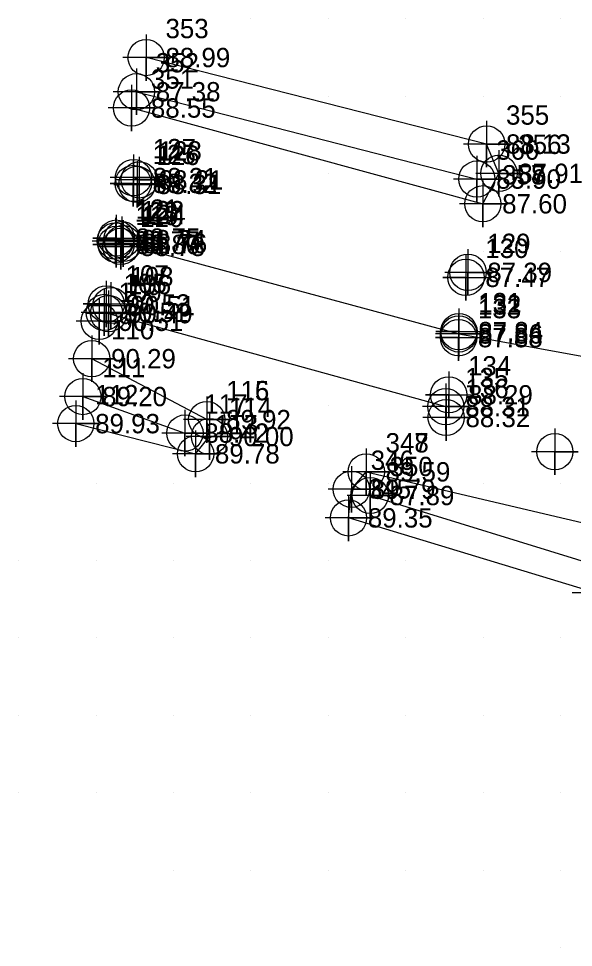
# Model space of a CAD drawing. Extents: x 1988140 to 1988766, y 249950 to 250250.
# Drawn here: x 1988140 to 1988211.7, y 249980 to 250100.1 of the extents above; entities that cross this region are included whole.
import ezdxf

# ---------------------------------------------------------------- set-up
doc = ezdxf.new("R2010")
doc.units = 0
for name, color, linetype in [('Exist DTM Breakline', 7, 'Continuous'), ('Exist DTM Breakline Cogo Elevation', 7, 'Continuous'), ('Exist DTM Breakline Cogo Number', 7, 'Continuous'), ('Exist DTM Breakline Cogo Point CELL', 7, 'Continuous'), ('Exist DTM Crownline', 7, 'Continuous'), ('Exist DTM Crownline Cogo Elevation', 7, 'Continuous'), ('Exist DTM Crownline Cogo Number', 7, 'Continuous'), ('Exist DTM Crownline Cogo Point CELL', 7, 'Continuous'), ('Exist DTM QL2 LIDAR Elevation Point', 7, 'Continuous'), ('Exist DTM Regular Point CELL', 7, 'Continuous'), ('Exist DTM Regular Point Cogo Elevation', 7, 'Continuous'), ('Exist DTM Regular Point Cogo Number', 7, 'Continuous'), ('Exist Roads EOP', 7, 'Continuous'), ('Exist Roads EOP Cogo Elevation', 7, 'Continuous'), ('Exist Roads EOP Cogo Number', 7, 'Continuous'), ('Exist Roads EOP Cogo Point CELL', 7, 'Continuous'), ('Exist Roads EOT', 7, 'Continuous'), ('Exist Roads EOT Cogo Elevation', 7, 'Continuous'), ('Exist Roads EOT Cogo Number', 7, 'Continuous'), ('Exist Roads EOT Cogo Point CELL', 7, 'Continuous')]:
    doc.layers.add(name, color=color, linetype=linetype)

msp = doc.modelspace()

# ---------------------------------------------------------------- linework, layer by layer
at = {"layer": 'Exist DTM Breakline'}
for p, q in [((1988155.2175, 250090.595), (1988199.1883, 250079.3107)), ((1988148.3042, 250051.201), (1988161.4866, 250046.4785))]:
    msp.add_line(p, q, dxfattribs=at)
for points in [[(1988154.5908, 250088.495), (1988199.964, 250076.113), (1988202.0406, 250080.0498), (1988200.4597, 250083.8363), (1988156.4732, 250095.0151)], [(1988147.3906, 250047.7015), (1988162.863, 250043.7963), (1988164.6596, 250046.0369), (1988164.3027, 250048.2184), (1988149.4523, 250056.0932)], [(1988182.6136, 250035.5158), (1988182.9813, 250039.2171), (1988184.903, 250041.4732), (1988219.3187, 250033.3718), (1988254.9783, 250021.8401), (1988300.1272, 250011.0374)], [(1988185.4236, 250038.4105), (1988216.1279, 250028.952), (1988254.719, 250017.0301), (1988298.2155, 250005.7241)], [(1988297.226, 250002.9987), (1988255.3705, 250011.301), (1988214.5049, 250025.8516), (1988182.6136, 250035.5158)]]:
    msp.add_lwpolyline(points, dxfattribs=at)
at = {"layer": 'Exist DTM Breakline Cogo Point CELL'}
for points in [[(1988156.4732, 250098.0151), (1988156.4732, 250092.0151), (1988156.4732, 250095.0151), (1988159.4732, 250095.0151), (1988153.4732, 250095.0151)], [(1988155.2175, 250093.595), (1988155.2175, 250087.595), (1988155.2175, 250090.595), (1988158.2175, 250090.595), (1988152.2175, 250090.595)], [(1988154.5908, 250091.495), (1988154.5908, 250085.495), (1988154.5908, 250088.495), (1988157.5908, 250088.495), (1988151.5908, 250088.495)], [(1988200.4597, 250086.8363), (1988200.4597, 250080.8363), (1988200.4597, 250083.8363), (1988203.4597, 250083.8363), (1988197.4597, 250083.8363)], [(1988199.1883, 250082.3107), (1988199.1883, 250076.3107), (1988199.1883, 250079.3107), (1988202.1883, 250079.3107), (1988196.1883, 250079.3107)], [(1988202.0406, 250083.0498), (1988202.0406, 250077.0498), (1988202.0406, 250080.0498), (1988205.0406, 250080.0498), (1988199.0406, 250080.0498)], [(1988199.964, 250079.113), (1988199.964, 250073.113), (1988199.964, 250076.113), (1988202.964, 250076.113), (1988196.964, 250076.113)], [(1988199.964, 250079.113), (1988199.964, 250073.113), (1988199.964, 250076.113), (1988202.964, 250076.113), (1988196.964, 250076.113)], [(1988149.4523, 250059.0932), (1988149.4523, 250053.0932), (1988149.4523, 250056.0932), (1988152.4523, 250056.0932), (1988146.4523, 250056.0932)], [(1988148.3042, 250054.201), (1988148.3042, 250048.201), (1988148.3042, 250051.201), (1988151.3042, 250051.201), (1988145.3042, 250051.201)], [(1988164.3027, 250051.2184), (1988164.3027, 250045.2184), (1988164.3027, 250048.2184), (1988167.3027, 250048.2184), (1988161.3027, 250048.2184)], [(1988164.3027, 250051.2184), (1988164.3027, 250045.2184), (1988164.3027, 250048.2184), (1988167.3027, 250048.2184), (1988161.3027, 250048.2184)], [(1988147.3906, 250050.7015), (1988147.3906, 250044.7015), (1988147.3906, 250047.7015), (1988150.3906, 250047.7015), (1988144.3906, 250047.7015)], [(1988161.4866, 250049.4785), (1988161.4866, 250043.4785), (1988161.4866, 250046.4785), (1988164.4866, 250046.4785), (1988158.4866, 250046.4785)], [(1988164.6596, 250049.0369), (1988164.6596, 250043.0369), (1988164.6596, 250046.0369), (1988167.6596, 250046.0369), (1988161.6596, 250046.0369)], [(1988162.863, 250046.7963), (1988162.863, 250040.7963), (1988162.863, 250043.7963), (1988165.863, 250043.7963), (1988159.863, 250043.7963)], [(1988184.903, 250044.4732), (1988184.903, 250038.4732), (1988184.903, 250041.4732), (1988187.903, 250041.4732), (1988181.903, 250041.4732)], [(1988184.903, 250044.4732), (1988184.903, 250038.4732), (1988184.903, 250041.4732), (1988187.903, 250041.4732), (1988181.903, 250041.4732)], [(1988182.9813, 250042.2171), (1988182.9813, 250036.2171), (1988182.9813, 250039.2171), (1988185.9813, 250039.2171), (1988179.9813, 250039.2171)], [(1988185.4236, 250041.4105), (1988185.4236, 250035.4105), (1988185.4236, 250038.4105), (1988188.4236, 250038.4105), (1988182.4236, 250038.4105)], [(1988182.6136, 250038.5158), (1988182.6136, 250032.5158), (1988182.6136, 250035.5158), (1988185.6136, 250035.5158), (1988179.6136, 250035.5158)], [(1988214.5049, 250028.8516), (1988214.5049, 250022.8516), (1988214.5049, 250025.8516), (1988217.5049, 250025.8516), (1988211.5049, 250025.8516)]]:
    msp.add_lwpolyline(points, dxfattribs=at)
for centre in [(1988156.4732, 250095.0151), (1988155.2175, 250090.595), (1988154.5908, 250088.495), (1988200.4597, 250083.8363), (1988202.0406, 250080.0498), (1988199.1883, 250079.3107), (1988199.964, 250076.113), (1988199.964, 250076.113), (1988149.4523, 250056.0932), (1988148.3042, 250051.201), (1988147.3906, 250047.7015), (1988164.3027, 250048.2184), (1988164.3027, 250048.2184), (1988161.4866, 250046.4785), (1988164.6596, 250046.0369), (1988162.863, 250043.7963), (1988184.903, 250041.4732), (1988184.903, 250041.4732), (1988182.9813, 250039.2171), (1988185.4236, 250038.4105), (1988182.6136, 250035.5158)]:
    msp.add_circle(centre, 2.344, dxfattribs=at)
at = {"layer": 'Exist DTM Crownline'}
msp.add_line((1988196.8572, 250059.2912), (1988232.2445, 250052.8974), dxfattribs=at)
msp.add_lwpolyline([(1988152.5012, 250071.3032), (1988196.8572, 250059.2912)], dxfattribs=at)
at = {"layer": 'Exist DTM Crownline Cogo Point CELL'}
for points in [[(1988152.5012, 250074.3032), (1988152.5012, 250068.3032), (1988152.5012, 250071.3032), (1988155.5012, 250071.3032), (1988149.5012, 250071.3032)], [(1988153.4965, 250073.9775), (1988153.4965, 250067.9775), (1988153.4965, 250070.9775), (1988156.4965, 250070.9775), (1988150.4965, 250070.9775)], [(1988196.8572, 250062.2912), (1988196.8572, 250056.2912), (1988196.8572, 250059.2912), (1988199.8572, 250059.2912), (1988193.8572, 250059.2912)]]:
    msp.add_lwpolyline(points, dxfattribs=at)
for centre in [(1988152.5012, 250071.3032), (1988153.4965, 250070.9775), (1988196.8572, 250059.2912)]:
    msp.add_circle(centre, 2.344, dxfattribs=at)
at = {"layer": 'Exist DTM QL2 LIDAR Elevation Point'}
for p, q in [((1988160, 250100), (1988160, 250100)), ((1988170, 250100), (1988170, 250100)), ((1988180, 250100), (1988180, 250100)), ((1988190, 250100), (1988190, 250100)), ((1988200, 250100), (1988200, 250100)), ((1988210, 250100), (1988210, 250100)), ((1988180, 250090), (1988180, 250090)), ((1988190, 250090), (1988190, 250090)), ((1988200, 250090), (1988200, 250090)), ((1988210, 250090), (1988210, 250090)), ((1988160, 250080), (1988160, 250080)), ((1988180, 250080), (1988180, 250080)), ((1988210, 250080), (1988210, 250080)), ((1988200, 250070), (1988200, 250070)), ((1988210, 250070), (1988210, 250070)), ((1988150, 250060), (1988150, 250060)), ((1988170, 250050), (1988170, 250050)), ((1988180, 250050), (1988180, 250050)), ((1988150, 250040), (1988150, 250040)), ((1988160, 250040), (1988160, 250040)), ((1988170, 250040), (1988170, 250040)), ((1988180, 250040), (1988180, 250040)), ((1988200, 250040), (1988200, 250040)), ((1988210, 250040), (1988210, 250040)), ((1988140, 250030), (1988140, 250030)), ((1988150, 250030), (1988150, 250030)), ((1988160, 250030), (1988160, 250030)), ((1988170, 250030), (1988170, 250030)), ((1988180, 250030), (1988180, 250030)), ((1988190, 250030), (1988190, 250030)), ((1988140, 250020), (1988140, 250020)), ((1988150, 250020), (1988150, 250020)), ((1988160, 250020), (1988160, 250020)), ((1988170, 250020), (1988170, 250020)), ((1988180, 250020), (1988180, 250020)), ((1988190, 250020), (1988190, 250020)), ((1988200, 250020), (1988200, 250020)), ((1988210, 250020), (1988210, 250020)), ((1988140, 250010), (1988140, 250010)), ((1988150, 250010), (1988150, 250010)), ((1988160, 250010), (1988160, 250010)), ((1988170, 250010), (1988170, 250010)), ((1988180, 250010), (1988180, 250010)), ((1988190, 250010), (1988190, 250010)), ((1988200, 250010), (1988200, 250010)), ((1988210, 250010), (1988210, 250010)), ((1988140, 250000), (1988140, 250000)), ((1988150, 250000), (1988150, 250000)), ((1988160, 250000), (1988160, 250000)), ((1988170, 250000), (1988170, 250000)), ((1988180, 250000), (1988180, 250000)), ((1988190, 250000), (1988190, 250000)), ((1988200, 250000), (1988200, 250000)), ((1988210, 250000), (1988210, 250000)), ((1988160, 249990), (1988160, 249990)), ((1988170, 249990), (1988170, 249990)), ((1988180, 249990), (1988180, 249990)), ((1988190, 249990), (1988190, 249990)), ((1988200, 249990), (1988200, 249990)), ((1988210, 249990), (1988210, 249990)), ((1988210, 249980), (1988210, 249980))]:
    msp.add_line(p, q, dxfattribs=at)
at = {"layer": 'Exist DTM Regular Point CELL'}
for points in [[(1988150.4184, 250063.925), (1988150.4184, 250057.925), (1988150.4184, 250060.925), (1988153.4184, 250060.925), (1988147.4184, 250060.925)], [(1988195.2245, 250051.4959), (1988195.2245, 250045.4959), (1988195.2245, 250048.4959), (1988198.2245, 250048.4959), (1988192.2245, 250048.4959)], [(1988209.2644, 250047.0711), (1988209.2644, 250041.0711), (1988209.2644, 250044.0711), (1988212.2644, 250044.0711), (1988206.2644, 250044.0711)]]:
    msp.add_lwpolyline(points, dxfattribs=at)
for centre in [(1988150.4184, 250060.925), (1988195.2245, 250048.4959), (1988209.2644, 250044.0711)]:
    msp.add_circle(centre, 2.344, dxfattribs=at)
at = {"layer": 'Exist Roads EOP'}
for p, q in [((1988154.8364, 250079.4949), (1988155.5906, 250079.2044)), ((1988151.0639, 250062.0678), (1988151.6279, 250061.9198)), ((1988151.6279, 250061.9198), (1988195.1839, 250049.8966))]:
    msp.add_line(p, q, dxfattribs=at)
at = {"layer": 'Exist Roads EOP Cogo Point CELL'}
for points in [[(1988154.8364, 250082.4949), (1988154.8364, 250076.4949), (1988154.8364, 250079.4949), (1988157.8364, 250079.4949), (1988151.8364, 250079.4949)], [(1988155.5906, 250082.2044), (1988155.5906, 250076.2044), (1988155.5906, 250079.2044), (1988158.5906, 250079.2044), (1988152.5906, 250079.2044)], [(1988198.0437, 250070.25), (1988198.0437, 250064.25), (1988198.0437, 250067.25), (1988201.0437, 250067.25), (1988195.0437, 250067.25)], [(1988151.0639, 250065.0678), (1988151.0639, 250059.0678), (1988151.0639, 250062.0678), (1988154.0639, 250062.0678), (1988148.0639, 250062.0678)], [(1988151.6279, 250064.9198), (1988151.6279, 250058.9198), (1988151.6279, 250061.9198), (1988154.6279, 250061.9198), (1988148.6279, 250061.9198)], [(1988195.1839, 250052.8966), (1988195.1839, 250046.8966), (1988195.1839, 250049.8966), (1988198.1839, 250049.8966), (1988192.1839, 250049.8966)]]:
    msp.add_lwpolyline(points, dxfattribs=at)
for centre in [(1988154.8364, 250079.4949), (1988155.5906, 250079.2044), (1988198.0437, 250067.25), (1988151.0639, 250062.0678), (1988151.6279, 250061.9198), (1988195.1839, 250049.8966)]:
    msp.add_circle(centre, 2.344, dxfattribs=at)
at = {"layer": 'Exist Roads EOT'}
msp.add_line((1988154.8117, 250078.7433), (1988155.3009, 250078.6196), dxfattribs=at)
at = {"layer": 'Exist Roads EOT Cogo Point CELL'}
for points in [[(1988154.8117, 250081.7433), (1988154.8117, 250075.7433), (1988154.8117, 250078.7433), (1988151.8117, 250078.7433), (1988157.8117, 250078.7433)], [(1988155.3009, 250081.6196), (1988155.3009, 250075.6196), (1988155.3009, 250078.6196), (1988152.3009, 250078.6196), (1988158.3009, 250078.6196)], [(1988152.6072, 250074.677), (1988152.6072, 250068.677), (1988152.6072, 250071.677), (1988149.6072, 250071.677), (1988155.6072, 250071.677)], [(1988153.3287, 250074.4752), (1988153.3287, 250068.4752), (1988153.3287, 250071.4752), (1988150.3287, 250071.4752), (1988156.3287, 250071.4752)], [(1988152.6043, 250073.8614), (1988152.6043, 250067.8614), (1988152.6043, 250070.8614), (1988149.6043, 250070.8614), (1988155.6043, 250070.8614)], [(1988153.2068, 250073.6075), (1988153.2068, 250067.6075), (1988153.2068, 250070.6075), (1988150.2068, 250070.6075), (1988156.2068, 250070.6075)], [(1988197.7859, 250069.6061), (1988197.7859, 250063.6061), (1988197.7859, 250066.6061), (1988194.7859, 250066.6061), (1988200.7859, 250066.6061)], [(1988151.3256, 250066.1626), (1988151.3256, 250060.1626), (1988151.3256, 250063.1626), (1988148.3256, 250063.1626), (1988154.3256, 250063.1626)], [(1988151.9316, 250065.965), (1988151.9316, 250059.965), (1988151.9316, 250062.965), (1988148.9316, 250062.965), (1988154.9316, 250062.965)], [(1988196.8732, 250062.5896), (1988196.8732, 250056.5896), (1988196.8732, 250059.5896), (1988193.8732, 250059.5896), (1988199.8732, 250059.5896)], [(1988196.8318, 250061.8149), (1988196.8318, 250055.8149), (1988196.8318, 250058.8149), (1988193.8318, 250058.8149), (1988199.8318, 250058.8149)], [(1988195.5553, 250054.4242), (1988195.5553, 250048.4242), (1988195.5553, 250051.4242), (1988192.5553, 250051.4242), (1988198.5553, 250051.4242)]]:
    msp.add_lwpolyline(points, dxfattribs=at)
for centre in [(1988154.8117, 250078.7433), (1988155.3009, 250078.6196), (1988152.6072, 250071.677), (1988152.6043, 250070.8614), (1988153.2068, 250070.6075), (1988153.3287, 250071.4752), (1988197.7859, 250066.6061), (1988151.3256, 250063.1626), (1988151.9316, 250062.965), (1988196.8732, 250059.5896), (1988196.8318, 250058.8149), (1988195.5553, 250051.4242)]:
    msp.add_circle(centre, 2.344, dxfattribs=at)

# ---------------------------------------------------------------- texts
at = {"layer": 'Exist DTM Breakline Cogo Elevation'}
for s, p in [('88.99', (1988158.9732, 250093.7651)), ('87.38', (1988157.7175, 250089.345)), ('88.55', (1988157.0908, 250087.245)), ('88.13', (1988202.9597, 250082.5863)), ('87.91', (1988204.5406, 250078.7998)), ('85.90', (1988201.6883, 250078.0607)), ('87.60', (1988202.464, 250074.863)), ('87.60', (1988202.464, 250074.863)), ('90.29', (1988151.9523, 250054.8432)), ('89.20', (1988150.8042, 250049.951)), ('89.93', (1988149.8906, 250046.4515)), ('89.92', (1988166.8027, 250046.9684)), ('89.92', (1988166.8027, 250046.9684)), ('88.42', (1988163.9866, 250045.2285)), ('90.00', (1988167.1596, 250044.7869)), ('89.78', (1988165.363, 250042.5463)), ('89.59', (1988187.403, 250040.2232)), ('89.59', (1988187.403, 250040.2232)), ('89.79', (1988185.4813, 250037.9671)), ('87.89', (1988187.9236, 250037.1605)), ('89.35', (1988185.1136, 250034.2658))]:
    msp.add_text(s, height=2.5, dxfattribs=at).set_placement(p)
at = {"layer": 'Exist DTM Breakline Cogo Number'}
for s, p in [('353', (1988158.9732, 250097.5151)), ('352', (1988157.7175, 250093.095)), ('351', (1988157.0908, 250090.995)), ('355', (1988202.9597, 250086.3363)), ('356', (1988204.5406, 250082.5498)), ('360', (1988201.6883, 250081.8107)), ('357', (1988202.464, 250078.613)), ('358', (1988202.464, 250078.613)), ('110', (1988151.9523, 250058.5932)), ('111', (1988150.8042, 250053.701)), ('112', (1988149.8906, 250050.2015)), ('116', (1988166.8027, 250050.7184)), ('115', (1988166.8027, 250050.7184)), ('117', (1988163.9866, 250048.9785)), ('114', (1988167.1596, 250048.5369)), ('113', (1988165.363, 250046.2963)), ('347', (1988187.403, 250043.9732)), ('348', (1988187.403, 250043.9732)), ('346', (1988185.4813, 250041.7171)), ('350', (1988187.9236, 250040.9105)), ('345', (1988185.1136, 250038.0158))]:
    msp.add_text(s, height=2.5, dxfattribs=at).set_placement(p)
at = {"layer": 'Exist DTM Crownline Cogo Elevation'}
for s, p in [('88.77', (1988155.0012, 250070.0532)), ('88.76', (1988155.9965, 250069.7275)), ('87.86', (1988199.3572, 250058.0412))]:
    msp.add_text(s, height=2.5, dxfattribs=at).set_placement(p)
at = {"layer": 'Exist DTM Crownline Cogo Number'}
for s, p in [('123', (1988155.0012, 250073.8032)), ('124', (1988155.9965, 250073.4775)), ('132', (1988199.3572, 250061.7912))]:
    msp.add_text(s, height=2.5, dxfattribs=at).set_placement(p)
at = {"layer": 'Exist DTM Regular Point Cogo Elevation'}
for s, p in [('90.51', (1988152.9184, 250059.675)), ('88.32', (1988197.7245, 250047.2459))]:
    msp.add_text(s, height=2.5, dxfattribs=at).set_placement(p)
at = {"layer": 'Exist DTM Regular Point Cogo Number'}
for s, p in [('109', (1988152.9184, 250063.425)), ('136', (1988197.7245, 250050.9959))]:
    msp.add_text(s, height=2.5, dxfattribs=at).set_placement(p)
at = {"layer": 'Exist Roads EOP Cogo Elevation'}
for s, p in [('88.21', (1988157.3364, 250078.2449)), ('88.21', (1988158.0906, 250077.9544)), ('87.39', (1988200.5437, 250066)), ('90.51', (1988153.5639, 250060.8178)), ('90.49', (1988154.1279, 250060.6698)), ('88.31', (1988197.6839, 250048.6466))]:
    msp.add_text(s, height=2.5, dxfattribs=at).set_placement(p)
at = {"layer": 'Exist Roads EOP Cogo Number'}
for s, p in [('127', (1988157.3364, 250081.9949)), ('128', (1988158.0906, 250081.7044)), ('129', (1988200.5437, 250069.75)), ('105', (1988153.5639, 250064.5678)), ('106', (1988154.1279, 250064.4198)), ('135', (1988197.6839, 250052.3966))]:
    msp.add_text(s, height=2.5, dxfattribs=at).set_placement(p)
at = {"layer": 'Exist Roads EOT Cogo Elevation'}
for s, p in [('88.32', (1988157.3117, 250077.4933)), ('88.31', (1988157.8009, 250077.3696)), ('88.75', (1988155.1072, 250070.427)), ('88.74', (1988155.8287, 250070.2252)), ('88.80', (1988155.1043, 250069.6114)), ('88.78', (1988155.7068, 250069.3575)), ('87.47', (1988200.2859, 250065.3561)), ('90.53', (1988153.8256, 250061.9126)), ('90.51', (1988154.4316, 250061.715)), ('87.84', (1988199.3732, 250058.3396)), ('87.88', (1988199.3318, 250057.5649)), ('88.29', (1988198.0553, 250050.1742))]:
    msp.add_text(s, height=2.5, dxfattribs=at).set_placement(p)
at = {"layer": 'Exist Roads EOT Cogo Number'}
for s, p in [('125', (1988157.3117, 250081.2433)), ('126', (1988157.8009, 250081.1196)), ('121', (1988155.1072, 250074.177)), ('122', (1988155.8287, 250073.9752)), ('119', (1988155.1043, 250073.3614)), ('120', (1988155.7068, 250073.1075)), ('130', (1988200.2859, 250069.1061)), ('107', (1988153.8256, 250065.6626)), ('108', (1988154.4316, 250065.465)), ('131', (1988199.3732, 250062.0896)), ('133', (1988199.3318, 250061.3149)), ('134', (1988198.0553, 250053.9242))]:
    msp.add_text(s, height=2.5, dxfattribs=at).set_placement(p)

doc.saveas('drawing.dxf')
